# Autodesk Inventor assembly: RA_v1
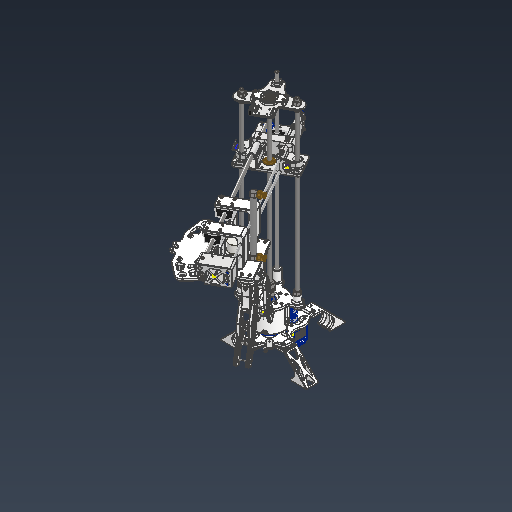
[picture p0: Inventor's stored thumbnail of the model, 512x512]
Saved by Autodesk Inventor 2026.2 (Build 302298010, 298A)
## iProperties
Created: 2026-04
Part Number: RA_v1
Document SubType Name: Assembly
Designer: work
Mass: 3600.07 g
Surface Area: 4552.63 cm^2
Volume: 1032.21 cm^3
Density: 3.48771 g/cm^3
Author: work
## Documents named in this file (45)
- C:\Users\khw\Desktop\ARD_v1\ARD_hardware\RA_Project\RA_v1.iam
- C:\Users\khw\Desktop\ARD_v1\ARD_hardware\RA_Project\48 Timing Belt Pulli.ipt
- C:\Users\khw\Desktop\ARD_v1\ARD_hardware\RA_Project\Y-axis - pulley support plate.ipt
- C:\Users\khw\Desktop\ARD_v1\ARD_hardware\RA_Project\Y-axis rotation plate.ipt
- C:\Users\khw\Desktop\ARD_v1\ARD_hardware\RA_Project\NEMA17.ipt
- C:\Users\khw\Desktop\ARD_v1\ARD_hardware\RA_Project\VL53L0X.ipt
- C:\Users\khw\Desktop\ARD_v1\ARD_hardware\RA_Project\X-axis fixing plate.ipt
- C:\Users\khw\Desktop\ARD_v1\ARD_hardware\RA_Project\JIS B 1521 - 625 5x16x5x1.73.ipt
- C:\Users\khw\Desktop\ARD_v1\ARD_hardware\RA_Project\5pi pin.ipt
- C:\Users\khw\Desktop\ARD_v1\ARD_hardware\RA_Project\X-axis disc support.ipt
- C:\Users\khw\Desktop\ARD_v1\ARD_hardware\RA_Project\T8linear shaft.ipt
- C:\Users\khw\Desktop\ARD_v1\ARD_hardware\RA_Project\T8Screws.ipt
- C:\Users\khw\Desktop\ARD_v1\ARD_hardware\RA_Project\8T_ScrewShaft.ipt
- C:\Users\khw\Desktop\ARD_v1\ARD_hardware\RA_Project\T8_BellowsCoulping.ipt
- C:\Users\khw\Desktop\ARD_v1\ARD_hardware\RA_Project\Y-axis End Leveler Mount.ipt
- C:\Users\khw\Desktop\ARD_v1\ARD_hardware\RA_Project\Y-axis end.ipt
- C:\Users\khw\Desktop\ARD_v1\ARD_hardware\RA_Project\Y-axis fixture.ipt
- C:\Users\khw\Desktop\ARD_v1\ARD_hardware\RA_Project\Y-axis Support fixing.ipt
- C:\Users\khw\Desktop\ARD_v1\ARD_hardware\RA_Project\T8_LeadNut.ipt
- C:\Users\khw\Desktop\ARD_v1\ARD_hardware\RA_Project\LeadWay.ipt
- C:\Users\khw\Desktop\ARD_v1\ARD_hardware\RA_Project\LimitedSwitch.ipt
- C:\Users\khw\Desktop\ARD_v1\ARD_hardware\RA_Project\24 Timing Belt Pulli.ipt
- C:\Users\khw\Desktop\ARD_v1\ARD_hardware\RA_Project\Al shaft 5pi-500mm.ipt
- C:\Users\khw\Desktop\ARD_v1\ARD_hardware\RA_Project\z-axis bearing puller support.ipt
- C:\Users\khw\Desktop\ARD_v1\ARD_hardware\RA_Project\end of the z-axis.ipt
- C:\Users\khw\Desktop\ARD_v1\ARD_hardware\RA_Project\KS B 1003 - M 3 x 16.ipt
- C:\Users\khw\Desktop\ARD_v1\ARD_hardware\RA_Project\KS B 1003 - M 2 x 10.ipt
- C:\Users\khw\Desktop\ARD_v1\ARD_hardware\RA_Project\JIS B 1521 - 623 3x10x4x0.630.ipt
- C:\Users\khw\Documents\Inventor\Content Center Files\R2026\ko-KR\KS B 1003\KS B 1003 - M 3 x 5.ipt
- C:\Users\khw\Desktop\ARD_v1\ARD_hardware\RA_Project\KS B 1003 - M 3 x 12.ipt
- C:\Users\khw\Documents\Inventor\Content Center Files\R2026\ko-KR\KS B 1003\KS B 1003 - M 2.5 x 4.ipt
- C:\Users\khw\Desktop\ARD_v1\ARD_hardware\RA_Project\KS B 1028 - M2.5x5(1).ipt
- C:\Users\khw\Desktop\ARD_v1\ARD_hardware\RA_Project\KS B 1028 - M3x5(1).ipt
- C:\Users\khw\Desktop\ARD_v1\ARD_hardware\RA_Project\KS B 1012 - C M8C.ipt
- C:\Users\khw\Desktop\ARD_v1\ARD_hardware\RA_Project\KS B 1003 - M 4 x 16.ipt
- C:\Users\khw\Desktop\ARD_v1\ARD_hardware\RA_Project\MPU-6050.ipt
- C:\Users\khw\Desktop\ARD_v1\ARD_hardware\RA_Project\Z-axis mover parts\Z-axis mover 2.ipt
- C:\Users\khw\Desktop\ARD_v1\ARD_hardware\RA_Project\Z-axis mover parts\Z-axis mover 1.ipt
- C:\Users\khw\Desktop\ARD_v1\ARD_hardware\RA_Project\JIS B 1521 - 608 8x22x7x3.3.ipt
- C:\Users\khw\Desktop\ARD_v1\ARD_hardware\RA_Project\KS B 1003 - M 1.6 x 2.5.ipt
- C:\Users\khw\Desktop\ARD_v1\ARD_hardware\RA_Project\Head\head stator.ipt
- C:\Users\khw\Desktop\ARD_v1\ARD_hardware\RA_Project\Head\GT2 Timing Belt Fixation.ipt
- C:\Users\khw\Desktop\ARD_v1\ARD_hardware\RA_Project\Head\Head connection and motor stator.ipt
- C:\Users\khw\Desktop\ARD_v1\ARD_hardware\RA_Project\28BJY-48.ipt
- C:\Users\khw\Desktop\ARD_v1\ARD_hardware\PneumaticGripper_v1\PneumaticGripper_v1.1.iam
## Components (166 placed, 44 different names)
1. 48 Timing Belt Pulli:1 — 플러쉬:1
2. Y-axis - pulley support plate:1
3. Y-axis rotation plate:1
4. NEMA17:1 — 각도:2
5. VL53L0X:1
6. X-axis fixing plate:1
7. NEMA17:2 — 플러쉬:4, 각도:9
8. 5pi pin:1 — 플러쉬:1
9. X-axis disc support:1
10. X-axis disc support:3
11. X-axis disc support:4
12. T8linear shaft:1
13. T8Screws:1 — 플러쉬:2
14. T8Screws:2 — 플러쉬:3
15. 8T_ScrewShaft:1 — 플러쉬:13
16. T8_BellowsCoulping:1
17. Y-axis End Leveler Mount:1 — 각도:3
18. Y-axis end:1
19. Y-axis fixture:1
20. Y-axis Support fixing:1
21. T8_LeadNut:1
22. LeadWay:1
23. LimitedSwitch:1 — 각도:4
24. 24 Timing Belt Pulli:1 — 플러쉬:4, 강체:2, 강체:3
25. T8linear shaft:2 — 플러쉬:11
26. NEMA17:3 — 플러쉬:6, 각도:7, 각도:9
27. 24 Timing Belt Pulli:2 — 플러쉬:6, 강체:4, 강체:5
28. Z-axis mover 2:1
29. Z-axis mover 1:1
30. MPU-6050:3
31. head stator:1
32. GT2 Timing Belt Fixation:1
33. GT2 Timing Belt Fixation:2
34. LeadWay:2
35. head stator:2
36. GT2 Timing Belt Fixation:3
37. GT2 Timing Belt Fixation:4
38. LeadWay:3
39. Head connection and motor stator:1
40. 28BJY-48:1
41. KS B 1003 - 미터 M 3 x 5:80
42. KS B 1003 - 미터 M 3 x 5:81
43. KS B 1003 - 미터 M 3 x 5:82
44. KS B 1003 - 미터 M 3 x 5:83
45. KS B 1003 - 미터 M 3 x 5:84
46. KS B 1003 - 미터 M 3 x 5:85
47. KS B 1003 - 미터 M 3 x 5:86
48. KS B 1003 - 미터 M 3 x 5:87
49. KS B 1003 - 미터 M 3 x 5:88
50. KS B 1003 - 미터 M 3 x 5:89
51. KS B 1003 - 미터 M 3 x 5:90
52. KS B 1003 - 미터 M 3 x 5:91
53. KS B 1003 - 미터 M 3 x 5:92
54. KS B 1003 - 미터 M 3 x 5:93
55. KS B 1003 - 미터 M 3 x 5:94
56. KS B 1003 - 미터 M 3 x 5:95
57. KS B 1003 - 미터 M 3 x 5:96
58. KS B 1003 - 미터 M 3 x 5:97
59. PneumaticGripper_v1.1:1 [sub-assembly] — 각도:10
60. JIS B 1521 - 625 5x16x5x1.73:1
61. KS B 1003 - 미터 M 3 x 5:76
62. KS B 1003 - 미터 M 3 x 5:77
63. KS B 1003 - 미터 M 3 x 5:78
64. KS B 1003 - 미터 M 3 x 5:79
65. KS B 1003 - 미터 M 3 x 5:72
66. KS B 1003 - 미터 M 3 x 5:73
67. KS B 1003 - 미터 M 3 x 5:74
68. KS B 1003 - 미터 M 3 x 5:75
69. KS B 1003 - 미터 M 3 x 5:68
70. KS B 1003 - 미터 M 3 x 5:69
71. KS B 1003 - 미터 M 3 x 5:70
72. KS B 1003 - 미터 M 3 x 5:71
73. KS B 1003 - 미터 M 3 x 5:64
74. KS B 1003 - 미터 M 3 x 5:65
75. KS B 1003 - 미터 M 3 x 5:66
76. KS B 1003 - 미터 M 3 x 5:67
77. JIS B 1521 - 608 8x22x7x3.3:1
78. KS B 1003 - 미터 M 3 x 5:44
79. KS B 1003 - 미터 M 3 x 5:45
80. KS B 1003 - 미터 M 3 x 5:46
81. KS B 1003 - 미터 M 3 x 5:47
82. KS B 1003 - 미터 M 3 x 5:48
83. KS B 1003 - 미터 M 3 x 5:49
84. KS B 1003 - 미터 M 3 x 5:50
85. KS B 1003 - 미터 M 3 x 5:51
86. KS B 1003 - 미터 M 3 x 5:52
87. KS B 1003 - 미터 M 3 x 5:53
88. KS B 1003 - 미터 M 3 x 5:54
89. KS B 1003 - 미터 M 3 x 5:55
90. KS B 1003 - 미터 M 3 x 5:56
91. KS B 1003 - 미터 M 3 x 5:57
92. KS B 1003 - 미터 M 3 x 5:58
93. KS B 1003 - 미터 M 3 x 5:59
94. KS B 1003 - 미터 M 3 x 5:60
95. KS B 1003 - 미터 M 3 x 5:61
96. KS B 1003 - 미터 M 3 x 5:62
97. KS B 1003 - 미터 M 3 x 5:63
98. KS B 1003 - 미터 M 2.5 x 4:3
99. KS B 1003 - 미터 M 2.5 x 4:4
100. KS B 1003 - 미터 M 2.5 x 4:5
101. KS B 1003 - 미터 M 2.5 x 4:6
102. KS B 1003 - M 1.6 x 2.5:1
103. KS B 1003 - M 1.6 x 2.5:2
104. KS B 1003 - M 1.6 x 2.5:3
105. KS B 1003 - M 1.6 x 2.5:4
106. Al shaft 5pi-500mm:1 — 플러쉬:10, 플러쉬:12
107. Al shaft 5pi-500mm:2 — 플러쉬:9
108. z-axis bearing puller support:1
109. end of the z-axis:1 — 플러쉬:9, 각도:6, 플러쉬:10, 플러쉬:11
110. KS B 1003 - M 3 x 16:1
111. KS B 1003 - M 2 x 10:1
112. KS B 1003 - M 2 x 10:2
113. JIS B 1521 - 623 3x10x4x0.630:1
114. JIS B 1521 - 623 3x10x4x0.630:2
115. VL53L0X:2 — 각도:8
116. LimitedSwitch:2 — 각도:6
117. KS B 1003 - M 3 x 12:1
118. KS B 1003 - 미터 M 3 x 5:1
119. KS B 1003 - 미터 M 3 x 5:2
120. KS B 1003 - 미터 M 3 x 5:3
121. KS B 1003 - 미터 M 3 x 5:4
122. KS B 1003 - 미터 M 3 x 5:5
123. KS B 1003 - 미터 M 3 x 5:6
124. KS B 1003 - 미터 M 3 x 5:7
125. KS B 1003 - 미터 M 3 x 5:8
126. KS B 1003 - 미터 M 3 x 5:9
127. KS B 1003 - 미터 M 2.5 x 4:1
128. KS B 1003 - 미터 M 2.5 x 4:2
129. KS B 1003 - 미터 M 3 x 5:10
130. KS B 1003 - 미터 M 3 x 5:11
131. KS B 1003 - 미터 M 3 x 5:12
132. KS B 1003 - 미터 M 3 x 5:13
133. KS B 1003 - 미터 M 3 x 5:14
134. KS B 1003 - 미터 M 3 x 5:15
135. KS B 1003 - 미터 M 3 x 5:16
136. KS B 1003 - 미터 M 3 x 5:17
137. KS B 1003 - 미터 M 3 x 5:18
138. KS B 1003 - 미터 M 3 x 5:19
139. KS B 1003 - 미터 M 3 x 5:20
140. KS B 1003 - 미터 M 3 x 5:21
141. KS B 1003 - 미터 M 3 x 5:36
142. KS B 1003 - 미터 M 3 x 5:37
143. KS B 1003 - 미터 M 3 x 5:38
144. KS B 1003 - 미터 M 3 x 5:39
145. KS B 1028 - M2.5x5(1):4 — 강체:2
146. KS B 1028 - M2.5x5(1):5 — 강체:3
147. KS B 1028 - M2.5x5(1):6 — 강체:4
148. KS B 1028 - M2.5x5(1):7 — 강체:5
149. KS B 1028 - M3x5(1):1 — 강체:7
150. KS B 1028 - M3x5(1):2 — 강체:6
151. KS B 1003 - 미터 M 3 x 5:40
152. KS B 1012 - C M8C:1
153. KS B 1012 - C M8C:2
154. KS B 1012 - C M8C:3
155. KS B 1012 - C M8C:4
156. KS B 1012 - C M8C:5
157. KS B 1012 - C M8C:6
158. KS B 1012 - C M8C:7
159. KS B 1012 - C M8C:8
160. KS B 1003 - 미터 M 3 x 5:41
161. KS B 1003 - M 4 x 16:1
162. KS B 1003 - M 4 x 16:2
163. KS B 1003 - M 4 x 16:3
164. KS B 1003 - M 4 x 16:4
165. KS B 1003 - 미터 M 3 x 5:42
166. KS B 1003 - 미터 M 3 x 5:43
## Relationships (24: Flush 10, Angle 8, WeldJoint 6)
- 플러쉬:1 [Flush]: 48 Timing Belt Pulli:1 ↔ 5pi pin:1
- 플러쉬:2 [Flush]: T8Screws:1
- 플러쉬:3 [Flush]: T8Screws:2
- 각도:2 [Angle]: NEMA17:1
- 각도:3 [Angle]: Y-axis End Leveler Mount:1
- 각도:4 [Angle]: LimitedSwitch:1
- 플러쉬:4 [Flush]: NEMA17:2 ↔ 24 Timing Belt Pulli:1
- 플러쉬:6 [Flush]: NEMA17:3 ↔ 24 Timing Belt Pulli:2
- 플러쉬:9 [Flush]: Al shaft 5pi-500mm:2 ↔ end of the z-axis:1
- 각도:6 [Angle]: end of the z-axis:1 ↔ LimitedSwitch:2
- 강체:2 [WeldJoint]: 24 Timing Belt Pulli:1 ↔ KS B 1028 - M2.5x5(1):4
- 강체:3 [WeldJoint]: 24 Timing Belt Pulli:1 ↔ KS B 1028 - M2.5x5(1):5
- 강체:4 [WeldJoint]: 24 Timing Belt Pulli:2 ↔ KS B 1028 - M2.5x5(1):6
- 강체:5 [WeldJoint]: 24 Timing Belt Pulli:2 ↔ KS B 1028 - M2.5x5(1):7
- 강체:6 [WeldJoint]: KS B 1028 - M3x5(1):2
- 강체:7 [WeldJoint]: KS B 1028 - M3x5(1):1
- 각도:7 [Angle]: NEMA17:3
- 플러쉬:10 [Flush]: Al shaft 5pi-500mm:1 ↔ end of the z-axis:1
- 플러쉬:11 [Flush]: T8linear shaft:2 ↔ end of the z-axis:1
- 플러쉬:12 [Flush]: Al shaft 5pi-500mm:1
- 플러쉬:13 [Flush]: 8T_ScrewShaft:1
- 각도:8 [Angle]: VL53L0X:2
- 각도:9 [Angle]: NEMA17:2 ↔ NEMA17:3
- 각도:10 [Angle]: PneumaticGripper_v1.1:1
## Named parameters: d444_d411 = 0, d445_d412 = 0, d446_d413 = 0, d447_d414 = 0, d448_d415 = 0, d449_d416 = 0, d450_d417 = 0, d451_d418 = 0, d452_d419 = 0, d453_d420 = 0, d454_d421 = 0, d455_d422 = 0, d456_d423 = 0, d457_d424 = 0, d458_d425 = 0, d459_d426 = 0, d460_d427 = 0, d461_d428 = 0, d462_d429 = 0, d463_d430 = 0, d464_d431 = 0, d465_d432 = 0, d466_d433 = 0, d467_d434 = 0, d468_d435 = 0, d469_d436 = 0, d470_d437 = 0, d471_d438 = 0, d472_d439 = 0, d473_d440 = 0, d474_d441 = 0, d475_d442 = 0, d476_d443 = 0
